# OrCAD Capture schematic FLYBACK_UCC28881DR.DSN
size A; title: Flyback Converter; rev: 1
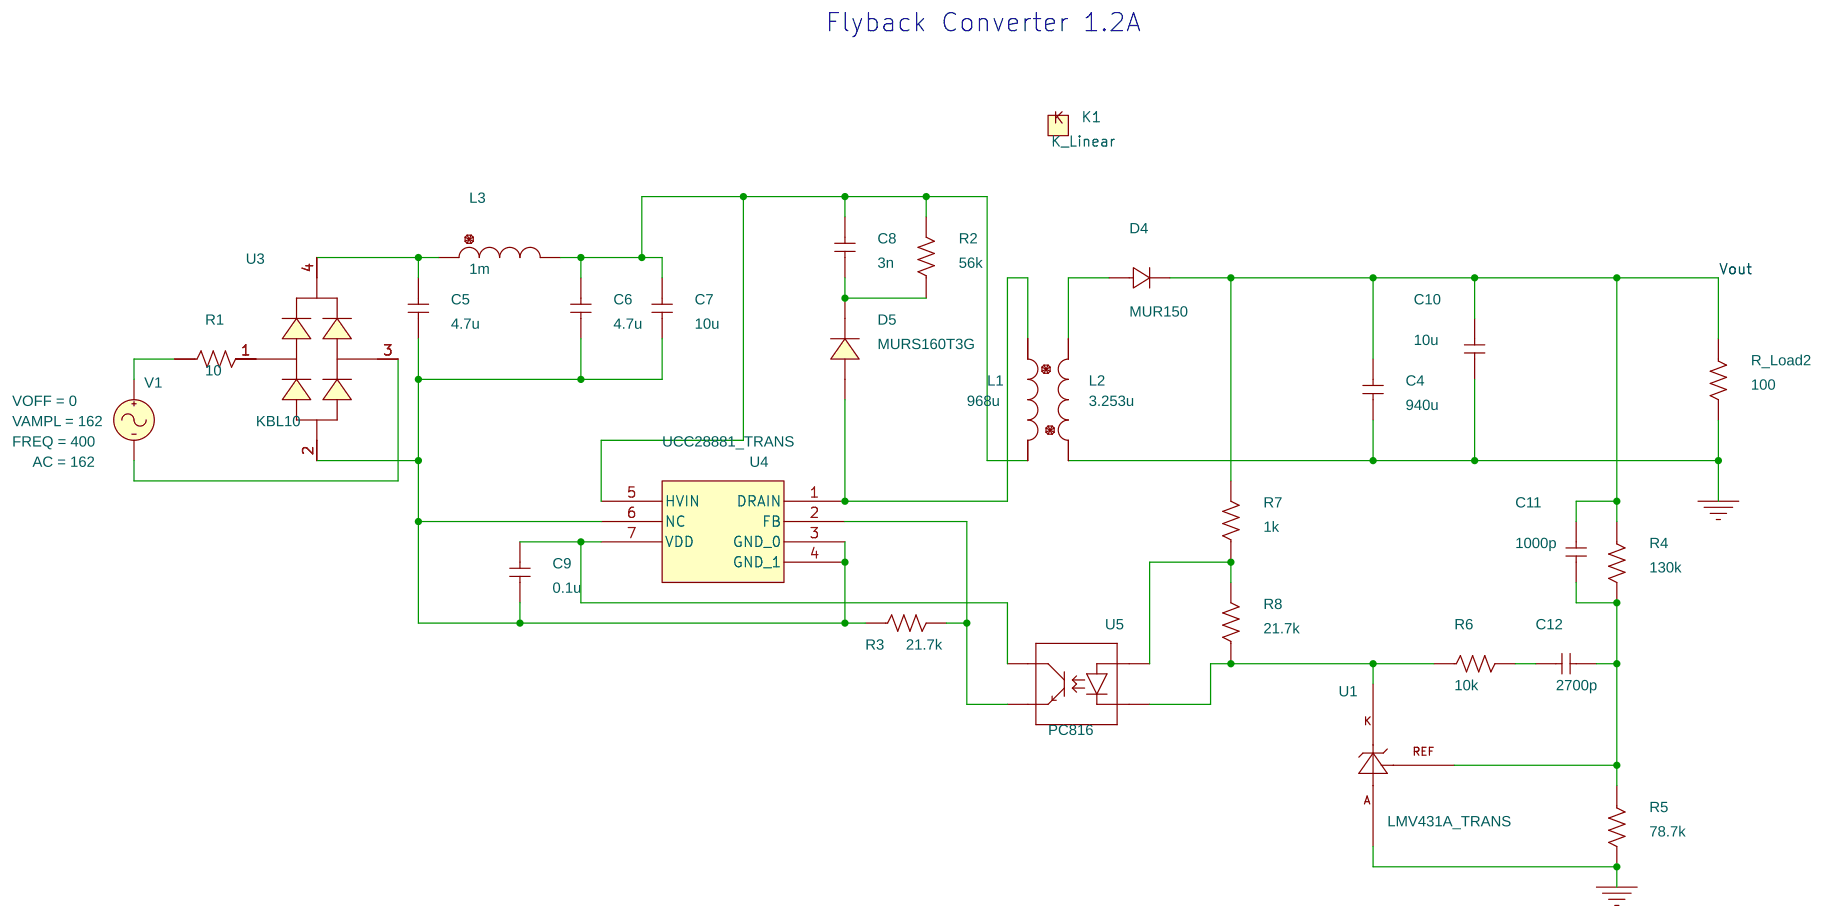
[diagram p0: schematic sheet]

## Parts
C4  940u  [RAD/CK05]
C5  4.7u  [RAD/CK05]
C6  4.7u  [RAD/CK05]
C7  10u  [RAD/CK05]
C8  3n  [RAD/CK05]
C9  0.1u  [RAD/CK05]
C10  10u  [RAD/CK05]
C11  1000p  [RAD/CK05]
C12  2700p  [RAD/CK05]
D4  MUR150  [DO-41]
D5  MURS160T3G  [SMB403A]
K1  K_Linear
L1  968u  [DISC/.350x.175/LS.200x.100/.034]
L2  3.253u  [DISC/.350x.175/LS.200x.100/.034]
L3  1m  [DISC/.350x.175/LS.200x.100/.034]
R1  10  [AX/RC05]
R2  56k  [AX/RC05]
R3  21.7k  [AX/RC05]
R4  130k  [AX/RC05]
R5  78.7k  [AX/RC05]
R6  10k  [AX/RC05]
R7  1k  [AX/RC05]
R8  21.7k  [AX/RC05]
R_Load2  100  [AX/RC05]
U1  LMV431A_TRANS  [Z03A]
U3  KBL10  [KBL]
U4  UCC28881_TRANS
U5  PC816  [DIP4_3]
V1  VSIN

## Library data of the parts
C4 C10-C12 = C: IC: 45
C5-C9 = C
D4 = MUR150
D5 = MURS160T3G
K1 = K_Linear: COUPLING: 1; L1: L1; L2: L2
L1-L3 = L
R1-R8 R_Load2 = R
U1 = LMV431A_TRANS
U3 = KBL10
U4 = UCC28881_TRANS
U5 = PC816
V1 = VSIN: AC: 162; DC: 0; FREQ: 400; VAMPL: 162; VOFF: 0

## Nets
0: C4.2 C10.1 L2.1 R5.2 R_Load2.2 U1.2(A)
Vout: C4.1 C10.2 C11.2 D4.2 R4.1 R7.2 R_Load2.1
N9030389: D5.2(A) L1.1 U4.1(DRAIN)
N9030687: D4.1 L2.2
N9041428: R1.2 U3.1(AC1)
N9041434: U3.3(AC2) V1.2(-)
N9041536: C5.2 L3.1 U3.4(+)
N9041542: C6.2 C7.2 C8.2 L1.2 L3.2 R2.2 U4.5(HVIN)
N9041550: C5.1 C6.1 C7.1 C9.2 R3.1 U3.2(-) U4.3(GND_0) U4.4(GND_1) U4.6(NC)
N9042501: C8.1 D5.1(C) R2.1
N9042929: R3.2 U4.2(FB) U5.3(C)
N9043207: C9.1 U4.7(VDD) U5.4(D)
N9044323: C11.1 C12.1 R4.2 R5.1 U1.1(REF)
N9044562: R7.1 R8.2 U5.1(A)
N9044590: C12.2 R6.2
N9044598: R6.1 R8.1 U1.3(K) U5.2(B)
N9045724: R1.1 V1.1(+)

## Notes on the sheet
- Flyback Converter 1.2A
